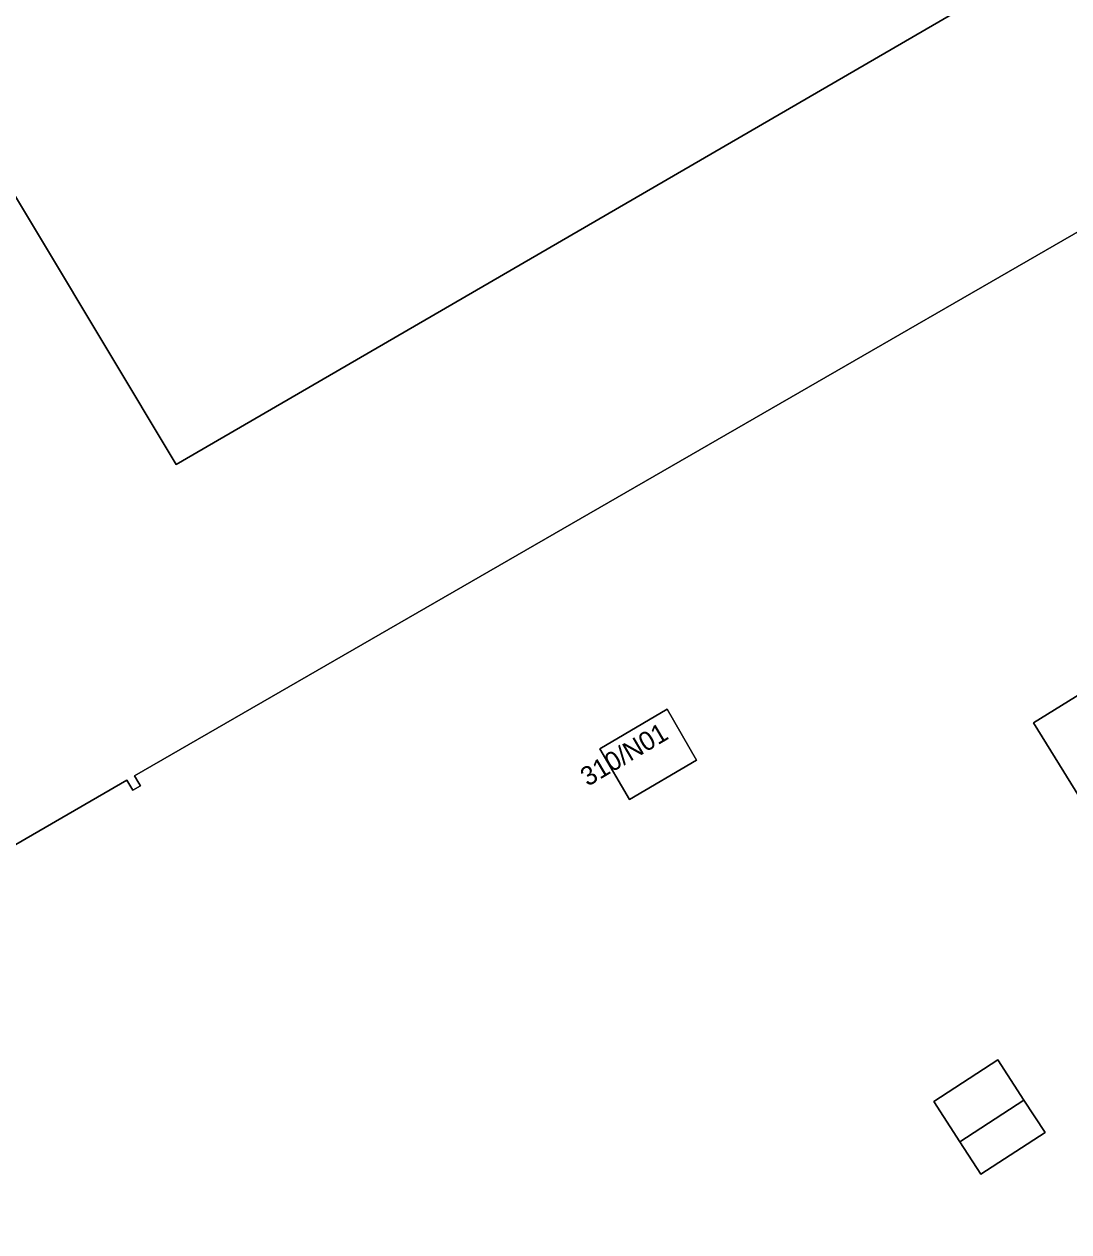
# Model space of a CAD drawing. Extents: x 160377 to 161131, y 383938 to 384853.
# Drawn here: x 160828.8 to 160884, y 384075.2 to 384139 of the extents above; entities that cross this region are included whole.
import ezdxf

# ---------------------------------------------------------------- set-up
doc = ezdxf.new("R2010")
doc.units = 0
for name, color, linetype in [('IMGEO_Erf', 7, 'Continuous'), ('IMGEO_Pand', 7, 'Continuous'), ('IMGEO_Pand_nummerreeks', 7, 'Continuous')]:
    doc.layers.add(name, color=color, linetype=linetype)

msp = doc.modelspace()

# ---------------------------------------------------------------- linework, layer by layer
at = {"layer": 'IMGEO_Erf'}
for points in [[(160822.309, 384139.961), (160836.83, 384115.751), (160887.477, 384145.158), (160873.867, 384168.808)], [(160860.808, 384098.035), (160859.247, 384100.722), (160862.795, 384102.815), (160864.356, 384100.128)], [(160879.398, 384078.224), (160878.283, 384079.941), (160876.902, 384082.067), (160880.295, 384084.27), (160881.676, 384082.142), (160882.79, 384080.426)]]:
    msp.add_lwpolyline(points, close=True, dxfattribs=at)
for points in [[(160890.527, 384131.513), (160834.633, 384099.302), (160834.861, 384098.913), (160834.947, 384098.767), (160834.542, 384098.529), (160834.226, 384099.067), (160824.893, 384093.669)], [(160888.883, 384091.279), (160882.188, 384102.104), (160900.865, 384113.655)]]:
    msp.add_lwpolyline(points, dxfattribs=at)
at = {"layer": 'IMGEO_Pand'}
msp.add_lwpolyline([(160894.342, 384153.219), (160882.131, 384174.376), (160883.487, 384175.131), (160881.533, 384178.537), (160881.486, 384178.803), (160880.079, 384177.999), (160875.749, 384185.481), (160866.157, 384179.985), (160866.843, 384178.831), (160861.65, 384175.828), (160860.985, 384176.98), (160807.194, 384145.974), (160813.295, 384135.382), (160808.456, 384132.612), (160803.964, 384130.039), (160806.458, 384125.706), (160824.893, 384093.669), (160834.226, 384099.067), (160834.542, 384098.529), (160834.947, 384098.767), (160834.861, 384098.913), (160834.633, 384099.302), (160890.527, 384131.513)], dxfattribs=at)
for points in [[(160887.477, 384145.158), (160836.83, 384115.751), (160822.309, 384139.961), (160873.867, 384168.808)], [(160897.344, 384119.696), (160900.145, 384114.822), (160900.865, 384113.655), (160882.188, 384102.104), (160888.883, 384091.279), (160894.425, 384094.704), (160901.87, 384082.71), (160898.237, 384080.466), (160902.53, 384073.486), (160926.821, 384088.57), (160924.142, 384092.631), (160930.835, 384096.766), (160922.351, 384110.497), (160922.933, 384110.829), (160919.226, 384116.769), (160918.666, 384116.419), (160914.283, 384123.494), (160913.749, 384123.162), (160911.27, 384127.462), (160907.84, 384125.465)], [(160862.795, 384102.815), (160859.247, 384100.722), (160860.808, 384098.035), (160864.356, 384100.128)], [(160881.676, 384082.142), (160880.295, 384084.27), (160876.902, 384082.067), (160878.283, 384079.941)], [(160879.398, 384078.224), (160882.79, 384080.426), (160881.676, 384082.142), (160878.283, 384079.941)]]:
    msp.add_lwpolyline(points, close=True, dxfattribs=at)

# ---------------------------------------------------------------- texts
at = {"layer": 'IMGEO_Pand_nummerreeks'}
msp.add_text('310/N01', height=1, rotation=30.64407, dxfattribs=at).set_placement((160858.598, 384098.708))

doc.saveas('drawing.dxf')
